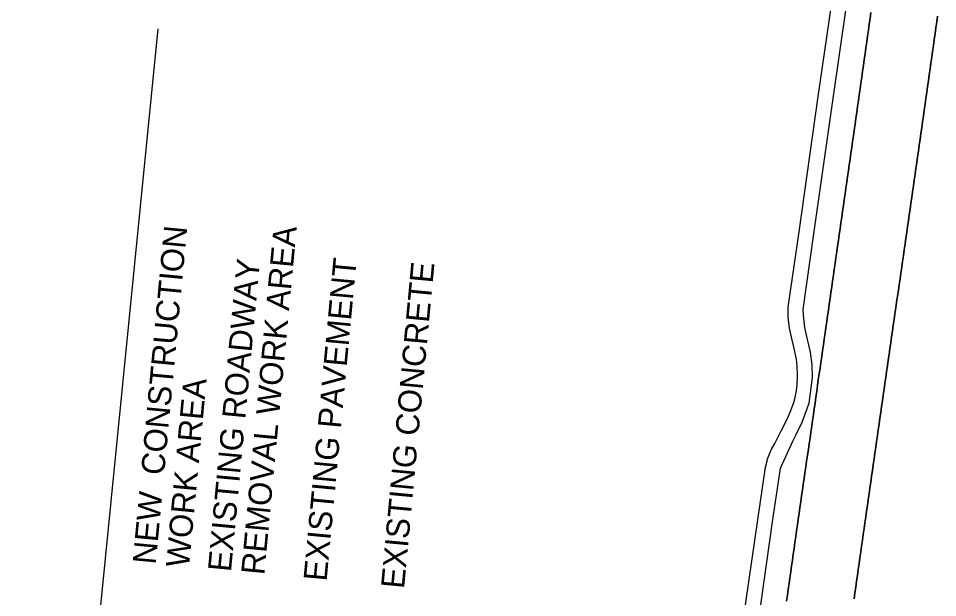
# Model space of a CAD drawing. Extents: x 1795987 to 1799700, y 243690 to 251545.
# Drawn here: x 1797261.4 to 1797570.3, y 247453.1 to 247647.8 of the extents above; entities that cross this region are included whole.
import ezdxf

# ---------------------------------------------------------------- set-up
doc = ezdxf.new("R2010")
doc.units = 0
for name, color, linetype in [('EP', 7, 'Continuous'), ('LEGEND', 7, 'Continuous'), ('Level 62', 7, 'Continuous')]:
    doc.layers.add(name, color=color, linetype=linetype)

msp = doc.modelspace()

# ---------------------------------------------------------------- linework, layer by layer
at = {"layer": 'EP'}
for points in [[(1797502.98, 247431.42), (1797509.89, 247479.28), (1797512.41, 247496.92), (1797513.21, 247499.92), (1797514.39, 247502.79), (1797515.55, 247504.9), (1797517.77, 247509.13), (1797519.86, 247513.31), (1797520.78, 247515.42), (1797521.93, 247518.67), (1797522.28, 247519.96), (1797522.83, 247522.6), (1797523.1, 247524.61), (1797523.26, 247527.63), (1797523.1, 247531.02), (1797522.82, 247533.27), (1797521.91, 247537.81), (1797521.35, 247540.15), (1797520.54, 247543.7), (1797520.12, 247547.31), (1797520.09, 247550.71), (1797523.74, 247576.05), (1797530.2, 247621.54), (1797536.99, 247668.47)], [(1797541.84, 247667.67), (1797535.11, 247620.83), (1797528.62, 247575.39), (1797524.96, 247549.93), (1797525.06, 247548.02), (1797525.55, 247543.91), (1797526.45, 247539.86), (1797526.65, 247538.96), (1797527.41, 247535.59), (1797527.98, 247531.38), (1797528.16, 247527.13), (1797526.97, 247518.48), (1797526.28, 247516.25), (1797524.64, 247511.95), (1797522.63, 247507.8), (1797522.17, 247506.93), (1797521.53, 247505.59), (1797517.43, 247496.48), (1797514.72, 247478.52), (1797507.92, 247430.67)]]:
    msp.add_lwpolyline(points, dxfattribs=at)
at = {"layer": 'LEGEND'}
msp.add_line((1797261.35, 247170.53), (1797308.29, 247644.28), dxfattribs=at)
at = {"layer": 'Level 62'}
for points in [[(1797519.54, 247451.89), (1797519.82, 247453.87), (1797520.1, 247455.84), (1797520.38, 247457.81), (1797520.66, 247459.79), (1797520.94, 247461.76), (1797521.23, 247463.73), (1797521.51, 247465.7), (1797521.79, 247467.68), (1797522.07, 247469.65), (1797522.35, 247471.62), (1797522.63, 247473.59), (1797522.91, 247475.55), (1797523.2, 247477.5), (1797523.48, 247479.45), (1797523.76, 247481.4), (1797524.04, 247483.36), (1797524.32, 247485.31), (1797524.6, 247487.26), (1797524.88, 247489.21), (1797525.16, 247491.17), (1797525.44, 247493.12), (1797525.72, 247495.07), (1797526, 247497.02), (1797526.28, 247498.98), (1797526.56, 247500.93), (1797526.85, 247502.88), (1797527.13, 247504.83), (1797527.41, 247506.79), (1797527.69, 247508.74), (1797527.97, 247510.69), (1797528.25, 247512.64), (1797528.53, 247514.6), (1797528.81, 247516.55), (1797529.09, 247518.5), (1797529.37, 247520.45), (1797529.65, 247522.41), (1797529.93, 247524.36), (1797530.21, 247526.31), (1797530.49, 247528.26), (1797530.78, 247530.22), (1797531.06, 247532.17), (1797531.34, 247534.12), (1797531.62, 247536.07), (1797531.9, 247538.03), (1797532.18, 247539.98), (1797532.46, 247541.93), (1797532.74, 247543.88), (1797533.02, 247545.84), (1797533.3, 247547.79), (1797533.58, 247549.74), (1797533.86, 247551.7), (1797534.14, 247553.65), (1797534.42, 247555.6), (1797534.71, 247557.55), (1797534.99, 247559.51), (1797535.27, 247561.46), (1797535.55, 247563.41), (1797535.83, 247565.36), (1797536.11, 247567.32), (1797536.39, 247569.27), (1797536.67, 247571.22), (1797536.95, 247573.17), (1797537.23, 247575.13), (1797537.51, 247577.08), (1797537.79, 247579.03), (1797538.07, 247580.98), (1797538.35, 247582.94), (1797538.64, 247584.89), (1797538.92, 247586.84), (1797539.2, 247588.79), (1797539.48, 247590.75), (1797539.76, 247592.7), (1797540.04, 247594.65), (1797540.32, 247596.6), (1797540.6, 247598.56), (1797540.88, 247600.51), (1797541.16, 247602.46), (1797541.44, 247604.41), (1797541.72, 247606.37), (1797542, 247608.32), (1797542.29, 247610.27), (1797542.57, 247612.24), (1797542.85, 247614.22), (1797543.13, 247616.19), (1797543.41, 247618.17), (1797543.69, 247620.14), (1797543.97, 247622.11), (1797544.25, 247624.09), (1797544.53, 247626.06), (1797544.81, 247628.04), (1797545.1, 247630.01), (1797545.38, 247631.98), (1797545.66, 247633.96), (1797545.94, 247635.93), (1797546.22, 247637.9), (1797546.5, 247639.88), (1797546.78, 247641.85), (1797547.06, 247643.83), (1797547.34, 247645.8), (1797547.63, 247647.77), (1797547.91, 247649.75)], [(1797547.91, 247649.75), (1797547.63, 247647.77), (1797547.34, 247645.8), (1797547.06, 247643.83), (1797546.78, 247641.85), (1797546.5, 247639.88), (1797546.22, 247637.9), (1797545.94, 247635.93), (1797545.66, 247633.96), (1797545.38, 247631.98), (1797545.1, 247630.01), (1797544.81, 247628.04), (1797544.53, 247626.06), (1797544.25, 247624.09), (1797543.97, 247622.11), (1797543.69, 247620.14), (1797543.41, 247618.17), (1797543.13, 247616.19), (1797542.85, 247614.22), (1797542.57, 247612.24), (1797542.29, 247610.27), (1797542, 247608.32), (1797541.72, 247606.37), (1797541.44, 247604.41), (1797541.16, 247602.46), (1797540.88, 247600.51), (1797540.6, 247598.56), (1797540.32, 247596.6), (1797540.04, 247594.65), (1797539.76, 247592.7), (1797539.48, 247590.75), (1797539.2, 247588.79), (1797538.92, 247586.84), (1797538.64, 247584.89), (1797538.35, 247582.94), (1797538.07, 247580.98), (1797537.79, 247579.03), (1797537.51, 247577.08), (1797537.23, 247575.13), (1797536.95, 247573.17), (1797536.67, 247571.22), (1797536.39, 247569.27), (1797536.11, 247567.32), (1797535.83, 247565.36), (1797535.55, 247563.41), (1797535.27, 247561.46), (1797534.99, 247559.51), (1797534.71, 247557.55), (1797534.42, 247555.6), (1797534.14, 247553.65), (1797533.86, 247551.7), (1797533.58, 247549.74), (1797533.3, 247547.79), (1797533.02, 247545.84), (1797532.74, 247543.88), (1797532.46, 247541.93), (1797532.18, 247539.98), (1797531.9, 247538.03), (1797531.62, 247536.07), (1797531.34, 247534.12), (1797531.06, 247532.17), (1797530.78, 247530.22), (1797530.49, 247528.26), (1797530.21, 247526.31), (1797529.93, 247524.36), (1797529.65, 247522.41), (1797529.37, 247520.45), (1797529.09, 247518.5), (1797528.81, 247516.55), (1797528.53, 247514.6), (1797528.25, 247512.64), (1797527.97, 247510.69), (1797527.69, 247508.74), (1797527.41, 247506.79), (1797527.13, 247504.83), (1797526.85, 247502.88), (1797526.56, 247500.93), (1797526.28, 247498.98), (1797526, 247497.02), (1797525.72, 247495.07), (1797525.44, 247493.12), (1797525.16, 247491.17), (1797524.88, 247489.21), (1797524.6, 247487.26), (1797524.32, 247485.31), (1797524.04, 247483.36), (1797523.76, 247481.4), (1797523.48, 247479.45), (1797523.2, 247477.5), (1797522.91, 247475.55), (1797522.63, 247473.59), (1797522.35, 247471.62), (1797522.07, 247469.65), (1797521.79, 247467.68), (1797521.51, 247465.7), (1797521.23, 247463.73), (1797520.94, 247461.76), (1797520.66, 247459.79), (1797520.38, 247457.81), (1797520.1, 247455.84), (1797519.82, 247453.87), (1797519.54, 247451.89)], [(1797570.3, 247648.55), (1797570.02, 247646.58), (1797569.74, 247644.61), (1797569.45, 247642.63), (1797569.17, 247640.66), (1797568.89, 247638.69), (1797568.61, 247636.71), (1797568.33, 247634.74), (1797568.05, 247632.77), (1797567.77, 247630.79), (1797567.49, 247628.82), (1797567.21, 247626.84), (1797566.92, 247624.87), (1797566.64, 247622.9), (1797566.36, 247620.92), (1797566.08, 247618.95), (1797565.8, 247616.98), (1797565.52, 247615), (1797565.24, 247613.03), (1797564.96, 247611.05), (1797564.68, 247609.08), (1797564.39, 247607.11), (1797564.11, 247605.15), (1797563.83, 247603.2), (1797563.55, 247601.25), (1797563.27, 247599.3), (1797562.99, 247597.34), (1797562.71, 247595.39), (1797562.43, 247593.44), (1797562.15, 247591.49), (1797561.87, 247589.53), (1797561.59, 247587.58), (1797561.31, 247585.63), (1797561.03, 247583.68), (1797560.75, 247581.72), (1797560.46, 247579.77), (1797560.18, 247577.82), (1797559.9, 247575.87), (1797559.62, 247573.91), (1797559.34, 247571.96), (1797559.06, 247570.01), (1797558.78, 247568.06), (1797558.5, 247566.1), (1797558.22, 247564.15), (1797557.94, 247562.2), (1797557.66, 247560.25), (1797557.38, 247558.29), (1797557.1, 247556.34), (1797556.81, 247554.39), (1797556.53, 247552.43), (1797556.25, 247550.48), (1797555.97, 247548.53), (1797555.69, 247546.58), (1797555.41, 247544.62), (1797555.13, 247542.67), (1797554.85, 247540.72), (1797554.57, 247538.77), (1797554.29, 247536.81), (1797554.01, 247534.86), (1797553.73, 247532.91), (1797553.45, 247530.96), (1797553.17, 247529), (1797552.88, 247527.05), (1797552.6, 247525.1), (1797552.32, 247523.15), (1797552.04, 247521.19), (1797551.76, 247519.24), (1797551.48, 247517.29), (1797551.2, 247515.34), (1797550.92, 247513.38), (1797550.64, 247511.43), (1797550.36, 247509.48), (1797550.08, 247507.53), (1797549.8, 247505.57), (1797549.52, 247503.62), (1797549.23, 247501.67), (1797548.95, 247499.72), (1797548.67, 247497.76), (1797548.39, 247495.81), (1797548.11, 247493.86), (1797547.83, 247491.91), (1797547.55, 247489.95), (1797547.27, 247488), (1797546.99, 247486.05), (1797546.71, 247484.09), (1797546.43, 247482.14), (1797546.15, 247480.19), (1797545.87, 247478.24), (1797545.59, 247476.28), (1797545.3, 247474.33), (1797545.02, 247472.38), (1797544.74, 247470.43), (1797544.46, 247468.45), (1797544.18, 247466.48), (1797543.9, 247464.51), (1797543.62, 247462.54), (1797543.34, 247460.56), (1797543.05, 247458.59), (1797542.77, 247456.62), (1797542.49, 247454.65), (1797542.21, 247452.67)], [(1797542.21, 247452.67), (1797542.49, 247454.65), (1797542.77, 247456.62), (1797543.05, 247458.59), (1797543.34, 247460.56), (1797543.62, 247462.54), (1797543.9, 247464.51), (1797544.18, 247466.48), (1797544.46, 247468.45), (1797544.74, 247470.43), (1797545.02, 247472.38), (1797545.3, 247474.33), (1797545.59, 247476.28), (1797545.87, 247478.24), (1797546.15, 247480.19), (1797546.43, 247482.14), (1797546.71, 247484.09), (1797546.99, 247486.05), (1797547.27, 247488), (1797547.55, 247489.95), (1797547.83, 247491.91), (1797548.11, 247493.86), (1797548.39, 247495.81), (1797548.67, 247497.76), (1797548.95, 247499.72), (1797549.23, 247501.67), (1797549.52, 247503.62), (1797549.8, 247505.57), (1797550.08, 247507.53), (1797550.36, 247509.48), (1797550.64, 247511.43), (1797550.92, 247513.38), (1797551.2, 247515.34), (1797551.48, 247517.29), (1797551.76, 247519.24), (1797552.04, 247521.19), (1797552.32, 247523.15), (1797552.6, 247525.1), (1797552.88, 247527.05), (1797553.17, 247529), (1797553.45, 247530.96), (1797553.73, 247532.91), (1797554.01, 247534.86), (1797554.29, 247536.81), (1797554.57, 247538.77), (1797554.85, 247540.72), (1797555.13, 247542.67), (1797555.41, 247544.62), (1797555.69, 247546.58), (1797555.97, 247548.53), (1797556.25, 247550.48), (1797556.53, 247552.43), (1797556.81, 247554.39), (1797557.1, 247556.34), (1797557.38, 247558.29), (1797557.66, 247560.25), (1797557.94, 247562.2), (1797558.22, 247564.15), (1797558.5, 247566.1), (1797558.78, 247568.06), (1797559.06, 247570.01), (1797559.34, 247571.96), (1797559.62, 247573.91), (1797559.9, 247575.87), (1797560.18, 247577.82), (1797560.46, 247579.77), (1797560.75, 247581.72), (1797561.03, 247583.68), (1797561.31, 247585.63), (1797561.59, 247587.58), (1797561.87, 247589.53), (1797562.15, 247591.49), (1797562.43, 247593.44), (1797562.71, 247595.39), (1797562.99, 247597.34), (1797563.27, 247599.3), (1797563.55, 247601.25), (1797563.83, 247603.2), (1797564.11, 247605.15), (1797564.39, 247607.11), (1797564.68, 247609.08), (1797564.96, 247611.05), (1797565.24, 247613.03), (1797565.52, 247615), (1797565.8, 247616.98), (1797566.08, 247618.95), (1797566.36, 247620.92), (1797566.64, 247622.9), (1797566.92, 247624.87), (1797567.21, 247626.84), (1797567.49, 247628.82), (1797567.77, 247630.79), (1797568.05, 247632.77), (1797568.33, 247634.74), (1797568.61, 247636.71), (1797568.89, 247638.69), (1797569.17, 247640.66), (1797569.45, 247642.63), (1797569.74, 247644.61), (1797570.02, 247646.58), (1797570.3, 247648.55)]]:
    msp.add_lwpolyline(points, dxfattribs=at)

# ---------------------------------------------------------------- texts
at = {"layer": 'LEGEND'}
for s, height, p in [('NEW  CONSTRUCTION', 7.7999, (1797307.5, 247464.07)), ('REMOVAL WORK AREA', 7.7999, (1797343.98, 247460.51)), ('EXISTING ROADWAY', 7.7999, (1797332.79, 247461.56)), ('EXISTING PAVEMENT', 7.7999, (1797364.92, 247458.39)), ('EXISTING CONCRETE', 7.7999, (1797390.96, 247455.89)), ('WORK AREA', 7.8, (1797318.69, 247463.02))]:
    msp.add_text(s, height=height, rotation=84.6544, dxfattribs=at).set_placement(p)

doc.saveas('drawing.dxf')
